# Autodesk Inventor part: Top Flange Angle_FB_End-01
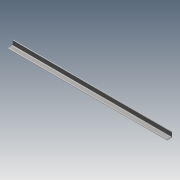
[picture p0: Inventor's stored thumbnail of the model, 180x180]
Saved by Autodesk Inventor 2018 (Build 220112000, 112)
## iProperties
Created: 2018-02
Part Number: Top Flange Angle_FB_End-01
Material: Steel, Mild
Document SubType Name: Modeling
Designer: STK
Mass: 216503 g
Surface Area: 46063.6 cm^2
Volume: 27580 cm^3
Density: 7.85 g/cm^3
Appearance: Semi-Polished
Author: STK
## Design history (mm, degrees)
derived "Top Flange Angle_FB_End.ipt"
feature "Solid1::Top Flange Angle_FB_End.ipt"
tag "TaggingFeature1"
body "Solid1"
